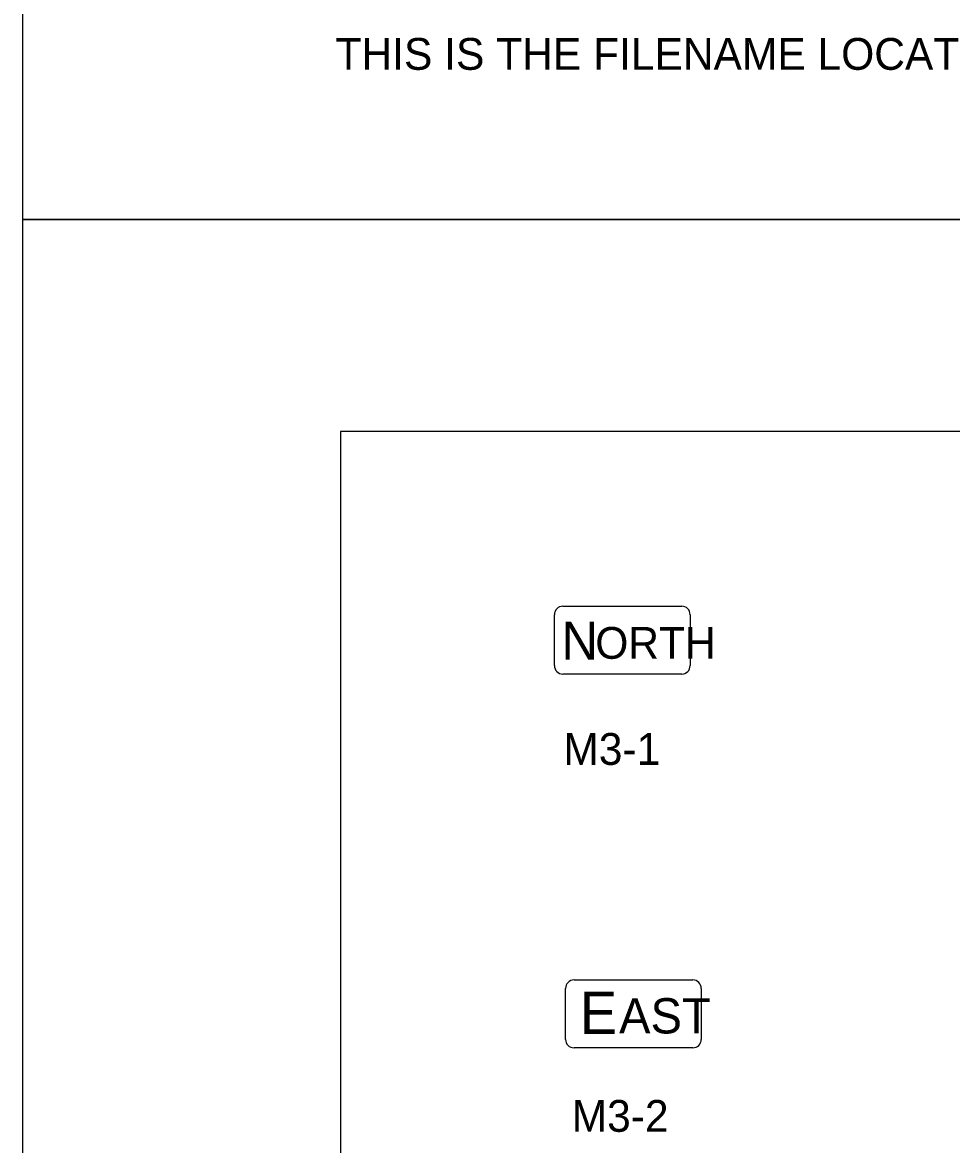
# Model space of a CAD drawing. Extents: x 42133 to 45533, y 41351 to 47951.
# Drawn here: x 42133.3 to 42352.5, y 45533.2 to 45797.8 of the extents above; entities that cross this region are included whole.
import ezdxf

# ---------------------------------------------------------------- set-up
doc = ezdxf.new("R2010")
doc.units = 0
for name, color, linetype in [('#plot_border', 7, 'Continuous'), ('#plot_shape', 7, 'Continuous'), ('P_ODOT_PLAN_Border', 7, 'Continuous'), ('P_TRAF_SIGN_SignDetails', 7, 'Continuous')]:
    doc.layers.add(name, color=color, linetype=linetype)

msp = doc.modelspace()

# ---------------------------------------------------------------- linework, layer by layer
at = {"layer": '#plot_shape'}
for points in [[(42133.34, 45751.35), (43833.34, 45751.35), (43833.34, 46851.35), (42133.34, 46851.35)], [(42133.34, 44651.35), (43833.34, 44651.35), (43833.34, 45751.35), (42133.34, 45751.35)]]:
    msp.add_lwpolyline(points, close=True, dxfattribs=at)
at = {"layer": 'P_ODOT_PLAN_Border'}
msp.add_lwpolyline([(42208.34, 44701.35), (43808.34, 44701.35), (43808.34, 45701.35), (42208.34, 45701.35)], close=True, dxfattribs=at)
at = {"layer": 'P_TRAF_SIGN_SignDetails'}
for p, q in [((42260.8, 45660.13), (42288.81, 45660.13)), ((42258.8, 45646.12), (42258.8, 45658.13)), ((42290.8, 45658.13), (42290.8, 45646.12)), ((42288.81, 45644.12), (42260.8, 45644.12)), ((42263.42, 45571.98), (42291.43, 45571.98)), ((42261.42, 45557.98), (42261.42, 45569.98)), ((42293.43, 45569.98), (42293.43, 45557.98)), ((42291.43, 45555.97), (42263.42, 45555.97))]:
    msp.add_line(p, q, dxfattribs=at)
for centre, start, end in [((42260.8, 45658.13), 90, 180), ((42288.81, 45658.13), 0, 90), ((42260.8, 45646.12), 180, 270), ((42288.81, 45646.12), 270, 0), ((42263.42, 45569.98), 90, 180), ((42291.43, 45569.98), 360, 90), ((42263.42, 45557.98), 180, 270), ((42291.43, 45557.98), 270, 0)]:
    msp.add_arc(centre, 2, start, end, dxfattribs=at)

# ---------------------------------------------------------------- texts
at = {"layer": '#plot_border'}
msp.add_text('THIS IS THE FILENAME LOCATION ##############################     DD-MMM-YYYY  HH:MM     USERNAME', height=7.5, dxfattribs=at).set_placement((42207.17, 45786.62))
at = {"layer": 'P_TRAF_SIGN_SignDetails'}
for s, height, p in [('N', 8.93, (42260.45, 45647.55)), ('ORTH', 7.491, (42268.44, 45647.73)), ('M3-1', 7.5, (42260.91, 45622.71)), ('E', 9.92, (42264.76, 45559.28)), ('AST', 8.323, (42274.04, 45559.37)), ('M3-2', 7.5, (42262.87, 45536.18))]:
    msp.add_text(s, height=height, dxfattribs=at).set_placement(p)

doc.saveas('drawing.dxf')
